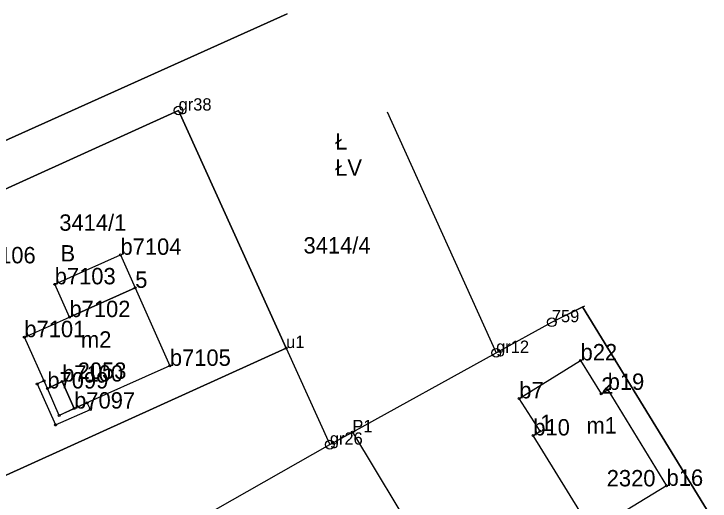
# Model space of a CAD drawing. Extents: x 7492083 to 7492670, y 5466693 to 5467065.
# Drawn here: x 7492163.8 to 7492227.5, y 5467020.8 to 5467065.4 of the extents above; entities that cross this region are included whole.
import ezdxf

# ---------------------------------------------------------------- set-up
doc = ezdxf.new("R2010")
doc.units = 0
for name, color, linetype in [('202-punkt graniczny', 7, 'Continuous'), ('202-punkt graniczny-Atr103', 7, 'Continuous'), ('203-punkt graniczny', 7, 'Continuous'), ('203-punkt graniczny-Atr103', 7, 'Continuous'), ('209-oznaczenie konturu klasyfikacyjnego', 7, 'Continuous'), ('210-oznaczenie konturu użytku gruntowego', 7, 'Continuous'), ('211-numer działki ewidencyjnej', 7, 'Continuous'), ('217-kontur klasyfikacyjny', 7, 'Continuous'), ('218-kontur użytku gruntowego', 7, 'Continuous'), ('219-działka ewidencyjna', 7, 'Continuous'), ('312-budynek ewidencyjny', 7, 'Continuous'), ('312-oznaczenie budynku ewidencyjnego', 7, 'Continuous'), ('312-oznaczenie budynku ewidencyjnego-Atr117', 7, 'Continuous'), ('320-blok - kondygnacja nadziemna', 7, 'Continuous'), ('352-schody', 7, 'Continuous'), ('blok - nawis', 7, 'Continuous'), ('Punkt budynku', 7, 'Continuous'), ('Punkt budynku-Atr103', 7, 'Continuous'), ('Punkt budynku-Atr104', 7, 'Continuous')]:
    doc.layers.add(name, color=color, linetype=linetype)

# ---------------------------------------------------------------- blocks, each defined once
blk = doc.blocks.new('202')
blk.add_circle((0, 0), 0.4)
blk = doc.blocks.new('203')
blk.add_circle((0, 0), 0.09)
blk = doc.blocks.new('PUNKTBUD')
blk.add_circle((0, 0), 0.09)

msp = doc.modelspace()

# ---------------------------------------------------------------- linework, layer by layer
at = {"layer": '217-kontur klasyfikacyjny'}
for points in [[(7492188.786, 5467065.383), (7492149.89, 5467047.92)], [(7492151.34, 5467044.08), (7492178.86, 5467056.54)], [(7492178.86, 5467056.54), (7492188.7, 5467034.81)], [(7492215.82, 5467038.58), (7492216.025, 5467038.684)], [(7492213.02, 5467037.17), (7492215.82, 5467038.58)], [(7492215.82, 5467038.58), (7492227.5, 5467019.53)], [(7492207.92, 5467034.37), (7492213.02, 5467037.17)], [(7492188.7, 5467034.81), (7492159.74, 5467021.69)], [(7492194.76, 5467027.11), (7492207.92, 5467034.37)], [(7492192.7, 5467025.97), (7492194.76, 5467027.11)], [(7492164.2, 5467009.8), (7492192.7, 5467025.97)]]:
    msp.add_lwpolyline(points, dxfattribs=at)
at = {"layer": '218-kontur użytku gruntowego'}
for points in [[(7492149.89, 5467047.92), (7492188.786, 5467065.383)], [(7492178.86, 5467056.54), (7492151.34, 5467044.08)], [(7492188.7, 5467034.81), (7492178.86, 5467056.54)], [(7492215.82, 5467038.58), (7492216.025, 5467038.684)], [(7492213.02, 5467037.17), (7492215.82, 5467038.58)], [(7492227.5, 5467019.53), (7492215.82, 5467038.58)], [(7492207.92, 5467034.37), (7492213.02, 5467037.17)], [(7492159.74, 5467021.69), (7492188.7, 5467034.81)], [(7492194.76, 5467027.11), (7492207.92, 5467034.37)], [(7492192.7, 5467025.97), (7492194.76, 5467027.11)], [(7492164.2, 5467009.8), (7492192.7, 5467025.97)]]:
    msp.add_lwpolyline(points, dxfattribs=at)
at = {"layer": '219-działka ewidencyjna'}
for points in [[(7492149.89, 5467047.92), (7492188.786, 5467065.383)], [(7492151.34, 5467044.08), (7492178.86, 5467056.54)], [(7492178.86, 5467056.54), (7492188.7, 5467034.81)], [(7492197.932, 5467056.418), (7492207.92, 5467034.37)], [(7492213.02, 5467037.17), (7492216.025, 5467038.684)], [(7492207.92, 5467034.37), (7492213.02, 5467037.17)], [(7492188.7, 5467034.81), (7492192.7, 5467025.97)], [(7492194.76, 5467027.11), (7492207.92, 5467034.37)], [(7492192.7, 5467025.97), (7492194.76, 5467027.11)], [(7492194.76, 5467027.11), (7492200.9, 5467016.91)], [(7492164.2, 5467009.8), (7492192.7, 5467025.97)]]:
    msp.add_lwpolyline(points, dxfattribs=at)
at = {"layer": '312-budynek ewidencyjny'}
for points in [[(7492167.52, 5467040.64), (7492173.54, 5467043.34)], [(7492173.54, 5467043.34), (7492174.89, 5467040.32)], [(7492168.87, 5467037.64), (7492167.52, 5467040.64)], [(7492174.89, 5467040.32), (7492178.06, 5467033.18)], [(7492164.74, 5467035.8), (7492168.87, 5467037.64)], [(7492166.85, 5467031.11), (7492164.74, 5467035.8)], [(7492210.04, 5467030.2), (7492215.65, 5467033.68)], [(7492215.65, 5467033.68), (7492217.54, 5467030.63)], [(7492178.06, 5467033.18), (7492169.3, 5467029.27)], [(7492168.2, 5467031.74), (7492166.85, 5467031.11)], [(7492169.3, 5467029.27), (7492168.2, 5467031.74)], [(7492217.54, 5467030.63), (7492218.13, 5467030.98)], [(7492218.13, 5467030.98), (7492223.52, 5467022.2)], [(7492211.95, 5467027.21), (7492210.04, 5467030.2)], [(7492211.32, 5467026.81), (7492211.95, 5467027.21)], [(7492216.7, 5467018.04), (7492211.32, 5467026.81)], [(7492223.52, 5467022.2), (7492216.7, 5467018.04)]]:
    msp.add_lwpolyline(points, dxfattribs=at)
at = {"layer": '320-blok - kondygnacja nadziemna'}
for points in [[(7492167.52, 5467040.64), (7492173.54, 5467043.34), (7492174.89, 5467040.32), (7492168.87, 5467037.64)], [(7492164.74, 5467035.8), (7492168.87, 5467037.64), (7492174.89, 5467040.32), (7492178.06, 5467033.18), (7492169.3, 5467029.27), (7492168.2, 5467031.74), (7492166.85, 5467031.11)]]:
    msp.add_lwpolyline(points, close=True, dxfattribs=at)
at = {"layer": '352-schody'}
msp.add_lwpolyline([(7492165.92, 5467031.52), (7492167.59, 5467027.77), (7492170.78, 5467029.18), (7492170.5, 5467029.8), (7492167.93, 5467028.64), (7492166.54, 5467031.8)], close=True, dxfattribs=at)
msp.add_lwpolyline([(7492165.92, 5467031.52), (7492167.59, 5467027.77), (7492170.78, 5467029.18), (7492170.5, 5467029.8), (7492167.93, 5467028.64), (7492166.54, 5467031.8)], close=True, dxfattribs=at)
at = {"layer": 'blok - nawis'}
msp.add_lwpolyline([(7492166.85, 5467031.11), (7492168.2, 5467031.74), (7492169.3, 5467029.27), (7492167.93, 5467028.64)], close=True, dxfattribs=at)

# ---------------------------------------------------------------- block references
at = {"layer": '202-punkt graniczny'}
for p in [(7492178.86, 5467056.54), (7492213.02, 5467037.17), (7492207.92, 5467034.37), (7492192.7, 5467025.97)]:
    msp.add_blockref('202', p, dxfattribs=at)
at = {"layer": '203-punkt graniczny'}
for p in [(7492188.7, 5467034.81), (7492194.76, 5467027.11)]:
    msp.add_blockref('203', p, dxfattribs=at)
at = {"layer": 'Punkt budynku'}
for p in [(7492173.54, 5467043.34), (7492167.52, 5467040.64), (7492174.89, 5467040.32), (7492168.87, 5467037.64), (7492164.74, 5467035.8), (7492215.65, 5467033.68), (7492178.06, 5467033.18), (7492165.92, 5467031.52), (7492166.54, 5467031.8), (7492168.2, 5467031.74), (7492166.85, 5467031.11), (7492218.13, 5467030.98), (7492217.54, 5467030.63), (7492170.5, 5467029.8), (7492210.04, 5467030.2), (7492169.3, 5467029.27), (7492170.78, 5467029.18), (7492167.93, 5467028.64), (7492167.59, 5467027.77), (7492211.95, 5467027.21), (7492211.32, 5467026.81), (7492223.52, 5467022.2)]:
    msp.add_blockref('PUNKTBUD', p, dxfattribs=at)

# ---------------------------------------------------------------- texts
at = {"layer": '202-punkt graniczny-Atr103'}
for s, p in [('gr38', (7492178.86, 5467056.54)), ('759', (7492213.02, 5467037.17)), ('gr12', (7492207.92, 5467034.37)), ('gr26', (7492192.7, 5467025.97))]:
    msp.add_text(s, height=1.125, dxfattribs=at).set_placement(p)
at = {"layer": '203-punkt graniczny-Atr103'}
for s, p in [('u1', (7492188.7, 5467034.81)), ('P1', (7492194.76, 5467027.11))]:
    msp.add_text(s, height=1.125, dxfattribs=at).set_placement(p)
at = {"layer": '209-oznaczenie konturu klasyfikacyjnego'}
msp.add_text('ŁV', height=1.5, dxfattribs=at).set_placement((7492193.19, 5467050.57))
at = {"layer": '210-oznaczenie konturu użytku gruntowego'}
for s, p in [('Ł', (7492193.19, 5467052.97)), ('B', (7492168.05, 5467042.73))]:
    msp.add_text(s, height=1.5, dxfattribs=at).set_placement(p)
at = {"layer": '211-numer działki ewidencyjnej'}
for s, p in [('3414/1', (7492167.94, 5467045.54)), ('3414/4', (7492190.29, 5467043.46))]:
    msp.add_text(s, height=1.5, dxfattribs=at).set_placement(p)
at = {"layer": '312-oznaczenie budynku ewidencyjnego'}
for s, p in [('2053', (7492169.62, 5467031.99)), ('2320', (7492218.04, 5467022.15))]:
    msp.add_text(s, height=1.5, dxfattribs=at).set_placement(p)
at = {"layer": '312-oznaczenie budynku ewidencyjnego-Atr117'}
for s, p in [('m2', (7492169.92, 5467034.84)), ('m1', (7492216.185, 5467026.99))]:
    msp.add_text(s, height=1.5, dxfattribs=at).set_placement(p)
at = {"layer": 'Punkt budynku-Atr103'}
for s, p in [('b7104', (7492173.54, 5467043.34)), ('b7106', (7492160.2, 5467042.56)), ('b7103', (7492167.52, 5467040.64)), ('b7102', (7492168.87, 5467037.64)), ('b7101', (7492164.74, 5467035.8)), ('b22', (7492215.65, 5467033.68)), ('b7105', (7492178.06, 5467033.18)), ('b7100', (7492168.2, 5467031.74)), ('b7099', (7492166.85, 5467031.11)), ('b19', (7492218.13, 5467030.98)), ('b7', (7492210.04, 5467030.2)), ('2', (7492217.54, 5467030.63)), ('b7097', (7492169.3, 5467029.27)), ('1', (7492211.95, 5467027.21)), ('b10', (7492211.32, 5467026.81)), ('b16', (7492223.52, 5467022.2))]:
    msp.add_text(s, height=1.5, dxfattribs=at).set_placement(p)
at = {"layer": 'Punkt budynku-Atr104'}
msp.add_text('5', height=1.5, dxfattribs=at).set_placement((7492174.89, 5467040.32))

doc.saveas('drawing.dxf')
